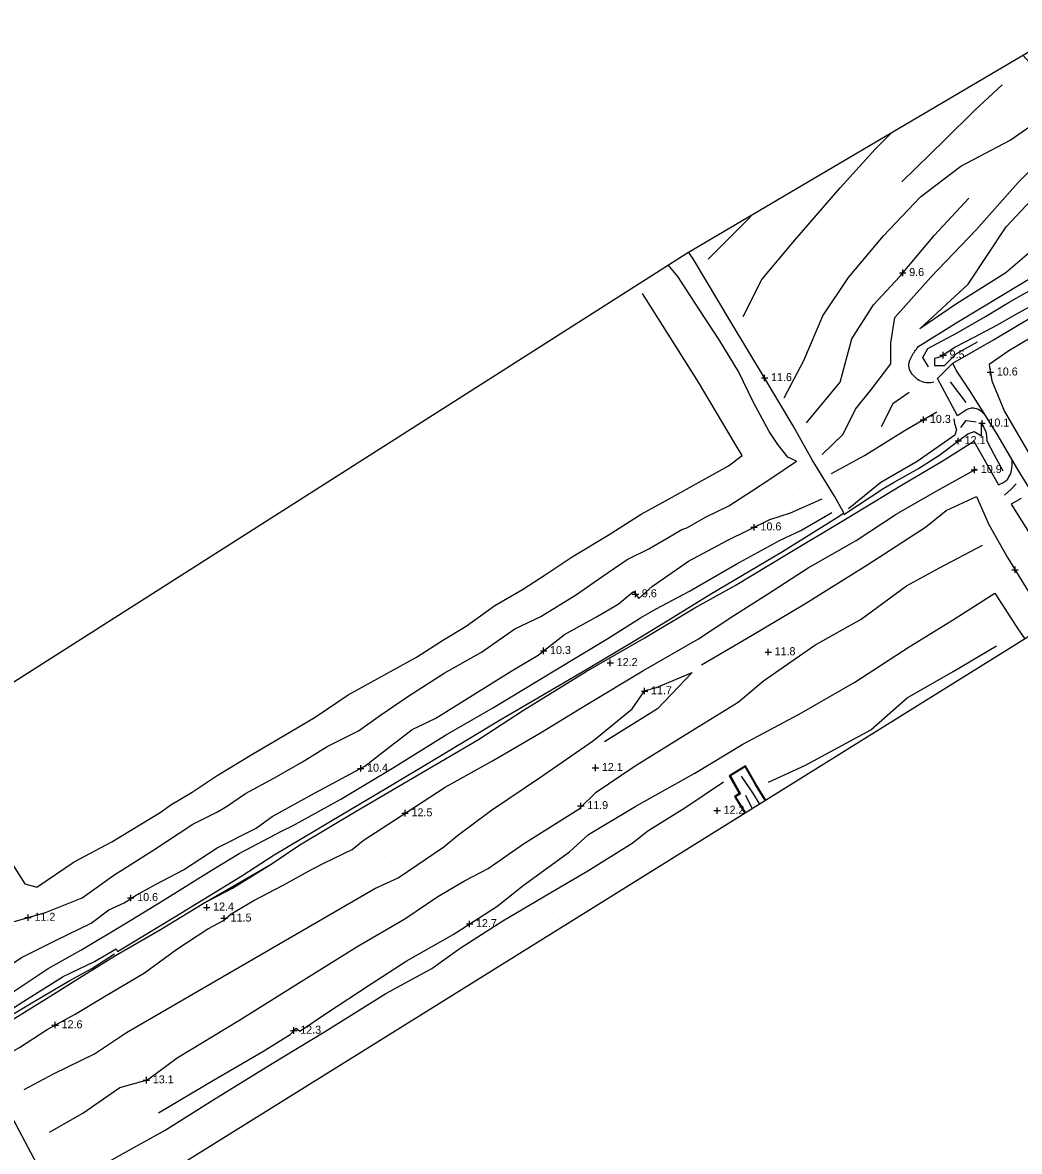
# Model space of a CAD drawing. Extents: x 2316231 to 2323598, y 363169 to 371906.
# Drawn here: x 2318197 to 2318819, y 368746 to 369451 of the extents above; entities that cross this region are included whole.
import ezdxf

# ---------------------------------------------------------------- set-up
doc = ezdxf.new("R2010")
doc.units = 0
for name, color, linetype in [('RD_DTM_BkLn1', 7, 'Continuous'), ('RD_DTM_Spot', 7, 'Continuous'), ('RD_DTM_TinHull', 7, 'Continuous'), ('RD_DTM_Void', 7, 'Continuous'), ('RD_EX_Road', 7, 'Continuous')]:
    doc.layers.add(name, color=color, linetype=linetype)

msp = doc.modelspace()

# ---------------------------------------------------------------- linework, layer by layer
at = {"layer": 'RD_DTM_BkLn1'}
for p, q in [((2318775.967, 369226.361), (2318785.842, 369213.429)), ((2318648.161, 368968.16), (2318652.337, 368959.64))]:
    msp.add_line(p, q, dxfattribs=at)
for points in [[(2318821.359, 369430.36), (2318833.929, 369416.318), (2318857.098, 369398.052), (2318876.357, 369378.589), (2318881.047, 369364.837), (2318878.846, 369345.713), (2318852.217, 369323.424), (2318829.708, 369310.579), (2318810.774, 369294.326), (2318779.947, 369275.055), (2318757.065, 369259.311), (2318787.149, 369287.192), (2318810.974, 369323.152), (2318829.939, 369343.202), (2318850.599, 369362.98), (2318851.312, 369380.511), (2318867.341, 369366.568), (2318854.815, 369340.791), (2318834.391, 369327.254)], [(2318745.754, 369351.081), (2318772.439, 369377.142), (2318791.386, 369395.915), (2318808.372, 369411.654)], [(2318672.457, 369216.258), (2318684.683, 369239.507), (2318696.612, 369267.472), (2318712.543, 369291.488), (2318734.369, 369317.42), (2318757.571, 369341.84), (2318782.715, 369360.973), (2318813.502, 369377.201), (2318833.127, 369390.992)], [(2318646.738, 369267.09), (2318658.497, 369290.078), (2318679.063, 369314.655), (2318707.239, 369347.357), (2318729.258, 369371.544), (2318739.835, 369382.275)], [(2318696.156, 369180.813), (2318709.127, 369193.648), (2318716.92, 369209.101), (2318727.145, 369221.844), (2318738.878, 369237.503), (2318738.899, 369250.681), (2318741.525, 369266.376), (2318763.849, 369291.732), (2318792.126, 369321.091), (2318818.401, 369350.83), (2318840.636, 369372.963)], [(2318686.257, 369200.608), (2318707.328, 369226.114), (2318714.681, 369253.184), (2318728.078, 369274.361), (2318744.561, 369292.12), (2318766.254, 369317.861), (2318787.707, 369340.881)], [(2318624.986, 369302.836), (2318649.023, 369327.096), (2318652.827, 369330.957)], [(2318318.77, 368957.723), (2318324.373, 368961.174), (2318336.268, 368969.133), (2318353.877, 368978.673), (2318371.753, 368989), (2318387.095, 368998.624), (2318406.746, 369008.273), (2318420.37, 369018.049), (2318437.477, 369029.753), (2318460.163, 369044.399), (2318483.473, 369057.538), (2318504.271, 369071.992), (2318520.582, 369079.772), (2318542.845, 369093.478), (2318558.505, 369104.544), (2318574.437, 369115.252), (2318587.901, 369122.009), (2318599.396, 369128.68), (2318608.425, 369134.1), (2318611.593, 369135.098), (2318623.626, 369142.006), (2318637.878, 369148.735), (2318651.977, 369158.019), (2318664.614, 369166.284), (2318680.163, 369176.779), (2318674.601, 369179.207), (2318668.507, 369187.106), (2318663.035, 369195.24), (2318653.26, 369213.459), (2318643.955, 369232.798), (2318632.274, 369251.839), (2318619.448, 369271.292), (2318606.057, 369291.965), (2318600.003, 369299.254)], [(2318762.396, 369235.636), (2318758.953, 369241.515), (2318762.061, 369246.99), (2318780.341, 369256.92), (2318798.121, 369267.164), (2318812.85, 369276.039), (2318827.134, 369284.153)], [(2318283.062, 368957.284), (2318289.69, 368962.204), (2318302.837, 368969.942), (2318318.494, 368980.519), (2318341.306, 368994.221), (2318360.427, 369005.33), (2318379.719, 369016.95), (2318400.359, 369030.891), (2318418.903, 369040.964), (2318442.895, 369054.421), (2318459.842, 369065.171), (2318474.008, 369073.679), (2318491.886, 369086.608), (2318508.996, 369096.533), (2318523.309, 369105.78), (2318540.092, 369117.032), (2318562.604, 369130.486), (2318583.169, 369143.699), (2318600.671, 369153.228), (2318620.737, 369164.534), (2318637.568, 369173.708), (2318646.161, 369180.169), (2318641.357, 369188.227), (2318618.971, 369226.018), (2318584.073, 369281.433)], [(2318826.841, 369273.793), (2318816.498, 369268.178), (2318805.278, 369261.612), (2318790.675, 369253.918), (2318779.065, 369248.01), (2318770.176, 369241.91), (2318766.135, 369240.761), (2318766.304, 369236.57), (2318772.499, 369236.514), (2318779.915, 369243.935), (2318793.144, 369251.302)], [(2318832.592, 369257.541), (2318812.619, 369245.59), (2318800.231, 369237.108), (2318802.052, 369226.964), (2318809.793, 369207.669), (2318825.043, 369181.817)], [(2318750.41, 369219.584), (2318740.178, 369212.452), (2318732.941, 369198.226)], [(2318701.907, 369169.084), (2318722.45, 369180.256), (2318747.982, 369196.034), (2318767.69, 369207.437)], [(2318709.65, 369143.355), (2318734.626, 369159.912), (2318741.031, 369163.578), (2318756.14, 369172.081), (2318769.615, 369180.784), (2318782.199, 369190.279), (2318786.932, 369193.728), (2318791.046, 369195.27), (2318795.568, 369192.513), (2318795.636, 369200.868), (2318798.444, 369194.622), (2318798.822, 369189.368), (2318803.243, 369181.061), (2318808.763, 369170.778)], [(2318782.632, 369197.833), (2318785.974, 369202.16), (2318792.141, 369201.316)], [(2318402.733, 368934.252), (2318409.74, 368939.752), (2318437.529, 368958.048), (2318460.766, 368973.121), (2318490.349, 368989.605), (2318520.259, 369007.09), (2318549.216, 369024.76), (2318584.098, 369045.788), (2318618.975, 369065.778), (2318641.04, 369080.403), (2318662.035, 369093.686), (2318687.284, 369110.05), (2318717.313, 369127.272), (2318742.18, 369143.709), (2318767.634, 369158.198), (2318792.32, 369171.998)], [(2318817.194, 369162.473), (2318813.906, 369159.136), (2318809.84, 369155.493)], [(2318342.854, 368947.622), (2318352.785, 368954.853), (2318379.326, 368969.479), (2318410.593, 368986.193), (2318422.064, 368995.241), (2318440.233, 369009.087), (2318454.977, 369016.22), (2318477.588, 369030.425), (2318502.965, 369046.119), (2318518.927, 369055.645), (2318535.313, 369068.498), (2318555.353, 369079.518), (2318568.859, 369087.361), (2318578.462, 369095.236), (2318581.674, 369091.006), (2318590.309, 369098.624), (2318612.582, 369114.275), (2318636.798, 369127.123), (2318663.391, 369140.34), (2318676.317, 369144.51), (2318696.094, 369153.179)], [(2318620.752, 369049.439), (2318652.447, 369068.132), (2318685.364, 369087.678), (2318724.622, 369112.217), (2318760.651, 369135.591), (2318773.455, 369145.992), (2318792.36, 369154.606), (2318800.146, 369137.114), (2318811.808, 369116.58), (2318830.247, 369086.414), (2318836.67, 369074.551)], [(2318358.747, 368945.649), (2318365.515, 368949.044), (2318395.767, 368965.752), (2318428.062, 368985.027), (2318461.092, 369005.599), (2318490.918, 369022.93), (2318528.795, 369045.769), (2318562.408, 369066.016), (2318582.697, 369078.86), (2318592.407, 369084.431), (2318613.307, 369095.494), (2318642.355, 369112.447), (2318669.828, 369127.355), (2318682.872, 369133.505), (2318702.137, 369144.72)], [(2318544.437, 368959.685), (2318555.063, 368970.106), (2318579.465, 368986.498), (2318616.711, 369009.662), (2318643.763, 369026.303), (2318659.435, 369039.566), (2318691.626, 369061.802), (2318720.408, 369078.159), (2318748.652, 369098.781), (2318769.278, 369110.024), (2318796.104, 369124.243)], [(2318538.409, 368932.692), (2318550.185, 368943.632), (2318579.786, 368961.226), (2318616.719, 368981.802), (2318646.49, 369000.028), (2318681.766, 369018.726), (2318716.513, 369038.8), (2318750.35, 369060.837), (2318777.474, 369077.37), (2318803.788, 369094.217), (2318818.721, 369071.471), (2318822.562, 369065.756)], [(2318662.671, 368976.32), (2318685.67, 368986.966), (2318726.454, 369008.906), (2318749.204, 369028.935), (2318777.89, 369045.305), (2318804.833, 369061.397)], [(2318459.925, 368935.824), (2318468.582, 368943.035), (2318489.746, 368958.883), (2318519.67, 368979.018), (2318553.395, 369002.38), (2318577.504, 369022.116), (2318585.442, 369033.426), (2318592.65, 369035.429), (2318615.069, 369044.825), (2318593.404, 369022.128), (2318560.218, 369001.425)], [(2318645.489, 368979.955), (2318652.537, 368969.629), (2318656.973, 368962.53)], [(2318577.558, 368938.118), (2318587.309, 368945.907), (2318610.315, 368960.218), (2318634.62, 368976.479)], [(2318069.796, 368913.667), (2318084.711, 368887.664), (2318096.568, 368861.51), (2318107.215, 368843.254), (2318128.886, 368852.799), (2318154.039, 368869.472), (2318177.979, 368887.147), (2318192.678, 368889.377), (2318211.476, 368894.92), (2318234.35, 368904.101), (2318254.106, 368918.162), (2318278.353, 368933.526), (2318303.385, 368950.103), (2318318.77, 368957.723)], [(2318213.86, 368757.804), (2318234.754, 368769.492), (2318257.787, 368785.628), (2318275.031, 368790.356), (2318293.619, 368804.155), (2318332.085, 368827.515), (2318374.324, 368853.935), (2318406.392, 368873.939), (2318435.674, 368891), (2318456.247, 368904.831), (2318472.828, 368914.627), (2318487.636, 368922.405), (2318509.681, 368937.665), (2318544.437, 368959.685)], [(2318182.938, 368937.212), (2318198.578, 368912.76), (2318205.987, 368910.734), (2318229.297, 368926.617), (2318252.791, 368939.057), (2318283.062, 368957.284)], [(2318057.547, 368908.988), (2318065.244, 368890.089), (2318075.451, 368863.434), (2318082.136, 368838.628), (2318084.803, 368825.3), (2318088.283, 368809.743), (2318118.752, 368824.828), (2318147.527, 368835.789), (2318174.581, 368852.254), (2318196.456, 368866.864), (2318218.021, 368877.528), (2318239.827, 368888.215), (2318250.977, 368896.519), (2318260.458, 368900.951), (2318268.087, 368905.712), (2318280.148, 368912.377), (2318297.498, 368921.473), (2318318.589, 368935.183), (2318342.854, 368947.622)], [(2318067.828, 368850.02), (2318072.967, 368828.154), (2318077.929, 368807.936), (2318084.572, 368796.477), (2318102.745, 368802.406), (2318129.775, 368813.72), (2318161.786, 368829.428), (2318186.859, 368842.43), (2318213.06, 368859.908), (2318233.376, 368871.453), (2318260.995, 368887.699), (2318284.458, 368902.258), (2318314.707, 368921.05), (2318332.361, 368931.626), (2318358.747, 368945.649)], [(2318231.245, 368728.124), (2318257.55, 368743.11), (2318285.998, 368758.946), (2318316.356, 368778.038), (2318352.81, 368800.5), (2318385.467, 368820.261), (2318423.718, 368844.319), (2318452.479, 368859.998), (2318470.209, 368872.547), (2318496.711, 368889.663), (2318530.355, 368909.507), (2318549.888, 368920.861), (2318577.558, 368938.118)], [(2318098.707, 368755.444), (2318123.229, 368769.712), (2318150.076, 368785.43), (2318172.668, 368797.801), (2318195.225, 368810.641), (2318212.484, 368821.831), (2318229.834, 368831.361), (2318248.296, 368842.501), (2318273.216, 368857.141), (2318293.274, 368871.923), (2318312.653, 368884.626), (2318322.461, 368889.888), (2318327.176, 368894.053), (2318341.431, 368902.458), (2318359.636, 368911.866), (2318377.83, 368921.923), (2318385.469, 368925.998), (2318402.733, 368934.252)], [(2318197.996, 368784.279), (2318216.9, 368794.31), (2318241.887, 368806.615), (2318261.882, 368819.954), (2318416.893, 368909.875), (2318431.53, 368916.583), (2318459.925, 368935.824)], [(2318281.834, 368769.75), (2318316.31, 368790.206), (2318347.074, 368808.046), (2318364.102, 368818.756), (2318367.829, 368822.695), (2318370.16, 368820.764), (2318386.189, 368831.512), (2318414.548, 368850.321), (2318436.458, 368864.546), (2318465.787, 368881.138), (2318493.132, 368898.697), (2318509.588, 368911.743), (2318538.409, 368932.692)], [(2318309.704, 368900.578), (2318328.017, 368910.142), (2318352.275, 368924.988)], [(2318082.182, 368776.745), (2318092.807, 368781.837), (2318111.618, 368792.976), (2318132.239, 368801.09), (2318157.872, 368811.637), (2318169.898, 368818.783), (2318201.892, 368837.824), (2318226.221, 368852.177), (2318240.223, 368859.969), (2318254.395, 368869.012)], [(2318128.541, 368755.619), (2318149.504, 368765.935), (2318167.781, 368775.367), (2318181.682, 368781.137), (2318192.93, 368762.507), (2318224.475, 368702.806), (2318242.058, 368675.521), (2318221.599, 368664.71), (2318205.84, 368656.549), (2318202.139, 368670.313), (2318152.285, 368755.23), (2318177.664, 368770.748)]]:
    msp.add_lwpolyline(points, dxfattribs=at)
at = {"layer": 'RD_DTM_Spot'}
for p, q in [((2318799.356, 369383.745), (2318799.356, 369383.745)), ((2318804.714, 369356.262), (2318804.714, 369356.262)), ((2318770.725, 369339.407), (2318770.725, 369339.407)), ((2318726.102, 369334.33), (2318726.102, 369334.33)), ((2318698.679, 369308.667), (2318698.679, 369308.667)), ((2318640.887, 369291.627), (2318640.887, 369291.627)), ((2318679.995, 369280.821), (2318679.995, 369280.821)), ((2318747.63, 369256.03), (2318747.63, 369256.03)), ((2318660.828, 369249.755), (2318660.828, 369249.755)), ((2318724.297, 369240.85), (2318724.297, 369240.85)), ((2318817.624, 369237.255), (2318817.624, 369237.255)), ((2318743.01, 369226.451), (2318743.01, 369226.451)), ((2318788.257, 369232.301), (2318788.257, 369232.301)), ((2318813.766, 369225.518), (2318813.766, 369225.518)), ((2318683.081, 369216.322), (2318683.081, 369216.322)), ((2318759.815, 369214.891), (2318759.815, 369214.891)), ((2318696.445, 369197.224), (2318696.445, 369197.224)), ((2318721.345, 369194.861), (2318721.345, 369194.861)), ((2318768.343, 369195.437), (2318768.343, 369195.437)), ((2318660.539, 369176.858), (2318660.539, 369176.858)), ((2318640.541, 369162.496), (2318640.541, 369162.496)), ((2318715.767, 369162.482), (2318715.767, 369162.482)), ((2318797.199, 369162.22), (2318797.199, 369162.22)), ((2318682.043, 369159.711), (2318682.043, 369159.711)), ((2318616.703, 369148.786), (2318616.703, 369148.786)), ((2318592.793, 369135.101), (2318592.793, 369135.101)), ((2318784.596, 369135.381), (2318784.596, 369135.381)), ((2318572.252, 369124.204), (2318572.252, 369124.204)), ((2318761.756, 369120.879), (2318761.756, 369120.879)), ((2318599.962, 369115.965), (2318599.962, 369115.965)), ((2318550.177, 369109.984), (2318550.177, 369109.984)), ((2318579.406, 369106.738), (2318579.406, 369106.738)), ((2318802.451, 369107.749), (2318802.451, 369107.749)), ((2318527.633, 369099.491), (2318527.633, 369099.491)), ((2318536.497, 369105.365), (2318536.497, 369105.365)), ((2318540.367, 369103.41), (2318540.367, 369103.41)), ((2318524.053, 369095.141), (2318524.053, 369095.141)), ((2318561.777, 369093.498), (2318561.777, 369093.498)), ((2318596.707, 369094.054), (2318596.707, 369094.054)), ((2318778.874, 369096.151), (2318778.874, 369096.151)), ((2318503.091, 369081.38), (2318503.091, 369081.38)), ((2318535.534, 369078.894), (2318535.534, 369078.894)), ((2318572.563, 369081.301), (2318572.563, 369081.301)), ((2318753.483, 369079.895), (2318753.483, 369079.895)), ((2318799.028, 369072.028), (2318799.028, 369072.028)), ((2318510, 369062.806), (2318510, 369062.806)), ((2318662.43, 369057.551), (2318662.43, 369057.551)), ((2318767.141, 369057.668), (2318767.141, 369057.668)), ((2318702.107, 369045.955), (2318702.107, 369045.955)), ((2318637.5, 369038.333), (2318637.5, 369038.333)), ((2318422.463, 369032.529), (2318422.463, 369032.529)), ((2318674.125, 369029.653), (2318674.125, 369029.653)), ((2318401.623, 369021.418), (2318401.623, 369021.418)), ((2318567.469, 369025.213), (2318567.469, 369025.213)), ((2318612.413, 369023.174), (2318612.413, 369023.174)), ((2318394.702, 369019.593), (2318394.702, 369019.593)), ((2318653.337, 369017.312), (2318653.337, 369017.312)), ((2318383.592, 369009.015), (2318383.592, 369009.015)), ((2318387.007, 369013.713), (2318387.007, 369013.713)), ((2318394.074, 369013.783), (2318394.074, 369013.783)), ((2318422.317, 369007.093), (2318422.317, 369007.093)), ((2318542.501, 369007.678), (2318542.501, 369007.678)), ((2318582.521, 369002.43), (2318582.521, 369002.43)), ((2318629.625, 369002.54), (2318629.625, 369002.54)), ((2318687.706, 369004.263), (2318687.706, 369004.263)), ((2318410.815, 368998.881), (2318410.815, 368998.881)), ((2318396.242, 368990.244), (2318396.242, 368990.244)), ((2318510.768, 368986.323), (2318510.768, 368986.323)), ((2318659.159, 368989.409), (2318659.159, 368989.409)), ((2318551.745, 368983.719), (2318551.745, 368983.719)), ((2318517.215, 368959.478), (2318517.215, 368959.478)), ((2318630.587, 368958.536), (2318630.587, 368958.536)), ((2318454.996, 368951.892), (2318454.996, 368951.892)), ((2318606.382, 368941.02), (2318606.382, 368941.02)), ((2318422.829, 368929.691), (2318422.829, 368929.691)), ((2318509.613, 368922.947), (2318509.613, 368922.947)), ((2318230.087, 368913.678), (2318230.087, 368913.678)), ((2318203.414, 368901.16), (2318203.414, 368901.16)), ((2318476.181, 368901.478), (2318476.181, 368901.478)), ((2318527.603, 368894.903), (2318527.603, 368894.903)), ((2318211.977, 368887.469), (2318211.977, 368887.469)), ((2318447.201, 368884.536), (2318447.201, 368884.536)), ((2318498.849, 368876.877), (2318498.849, 368876.877)), ((2318416.159, 368865.89), (2318416.159, 368865.89)), ((2318469.295, 368856.146), (2318469.295, 368856.146)), ((2318390.034, 368844.935), (2318390.034, 368844.935)), ((2318242.783, 368825.604), (2318242.783, 368825.604)), ((2318361.381, 368829.461), (2318361.381, 368829.461)), ((2318337.153, 368817.19), (2318337.153, 368817.19)), ((2318221.618, 368811.088), (2318221.618, 368811.088)), ((2318198.098, 368798.154), (2318198.098, 368798.154)), ((2318306.233, 368799.567), (2318306.233, 368799.567)), ((2318241.686, 368791.536), (2318241.686, 368791.536)), ((2318272.61, 368778.483), (2318272.61, 368778.483)), ((2318210.501, 368773.757), (2318210.501, 368773.757)), ((2318250.869, 368758.986), (2318250.869, 368758.986))]:
    msp.add_line(p, q, dxfattribs=at)
at = {"layer": 'RD_DTM_TinHull'}
for points in [[(2318500.627, 367718.473), (2317350.395, 369314.708), (2317732.783, 369650.329), (2318062.064, 369676.571), (2318100.376, 368980.922), (2318611.552, 369306.612), (2319043.87, 369561.601), (2319323.163, 369792.894), (2318905.258, 370457.792), (2319170.205, 370651.465)], [(2321400.963, 368599.408), (2321534.916, 368777.939), (2321271.463, 369044.178), (2321175.279, 369261.496), (2321099.267, 369551.406), (2321096.219, 369852.637), (2320858.06, 369744.011), (2320482.587, 369669.607), (2320232.924, 369604.892), (2319951.333, 369602.051), (2320092.085, 369259.27), (2319866.523, 369058.699), (2319771.694, 369171.639), (2319557.442, 369523.873), (2318254.179, 368711.432)]]:
    msp.add_lwpolyline(points, dxfattribs=at)
at = {"layer": 'RD_DTM_Void'}
for p, q in [((2318746.419, 369292.325), (2318746.419, 369296.325)), ((2318744.419, 369294.325), (2318748.419, 369294.325)), ((2318769.621, 369242.902), (2318773.621, 369242.902)), ((2318771.621, 369240.902), (2318771.621, 369244.902)), ((2318801.109, 369230.22), (2318801.109, 369234.22)), ((2318658.196, 369228.713), (2318662.196, 369228.713)), ((2318660.196, 369226.713), (2318660.196, 369230.713)), ((2318799.109, 369232.22), (2318803.109, 369232.22)), ((2318759.36, 369200.617), (2318759.36, 369204.617)), ((2318757.36, 369202.617), (2318761.36, 369202.617)), ((2318793.865, 369200.359), (2318797.865, 369200.359)), ((2318795.865, 369198.359), (2318795.865, 369202.359)), ((2318781.022, 369187.391), (2318781.022, 369191.391)), ((2318779.022, 369189.391), (2318783.022, 369189.391)), ((2318789.118, 369171.326), (2318793.118, 369171.326)), ((2318791.118, 369169.326), (2318791.118, 369173.326)), ((2318651.626, 369135.487), (2318655.626, 369135.487)), ((2318653.626, 369133.487), (2318653.626, 369137.487)), ((2318814.464, 369108.963), (2318818.464, 369108.963)), ((2318816.464, 369106.963), (2318816.464, 369110.963)), ((2318577.607, 369093.728), (2318581.607, 369093.728)), ((2318579.607, 369091.728), (2318579.607, 369095.728)), ((2318520.289, 369058.282), (2318524.289, 369058.282)), ((2318522.289, 369056.282), (2318522.289, 369060.282)), ((2318660.43, 369057.551), (2318664.43, 369057.551)), ((2318662.43, 369055.551), (2318662.43, 369059.551)), ((2318561.88, 369050.788), (2318565.88, 369050.788)), ((2318563.88, 369048.788), (2318563.88, 369052.788)), ((2318585.264, 369031.173), (2318585.264, 369035.173)), ((2318583.264, 369033.173), (2318587.264, 369033.173)), ((2318408.102, 368982.862), (2318408.102, 368986.862)), ((2318554.63, 368983.232), (2318554.63, 368987.232)), ((2318406.102, 368984.862), (2318410.102, 368984.862)), ((2318552.63, 368985.232), (2318556.63, 368985.232)), ((2318435.834, 368954.932), (2318435.834, 368958.932)), ((2318543.492, 368961.454), (2318547.492, 368961.454)), ((2318545.492, 368959.454), (2318545.492, 368963.454)), ((2318628.587, 368958.536), (2318632.587, 368958.536)), ((2318630.587, 368956.536), (2318630.587, 368960.536)), ((2318433.834, 368956.932), (2318437.834, 368956.932)), ((2318262.617, 368904.01), (2318266.617, 368904.01)), ((2318264.617, 368902.01), (2318264.617, 368906.01)), ((2318310.021, 368898.094), (2318314.021, 368898.094)), ((2318312.021, 368896.094), (2318312.021, 368900.094)), ((2318198.543, 368891.696), (2318202.543, 368891.696)), ((2318200.543, 368889.696), (2318200.543, 368893.696)), ((2318320.921, 368891.246), (2318324.921, 368891.246)), ((2318322.921, 368889.246), (2318322.921, 368893.246)), ((2318474.048, 368887.727), (2318478.048, 368887.727)), ((2318476.048, 368885.727), (2318476.048, 368889.727)), ((2318215.458, 368824.564), (2318219.458, 368824.564)), ((2318217.458, 368822.564), (2318217.458, 368826.564)), ((2318364.39, 368821.174), (2318368.39, 368821.174)), ((2318366.39, 368819.174), (2318366.39, 368823.174)), ((2318272.404, 368790.184), (2318276.404, 368790.184)), ((2318274.404, 368788.184), (2318274.404, 368792.184))]:
    msp.add_line(p, q, dxfattribs=at)
at = {"layer": 'RD_EX_Road'}
for points in [[(2318755.848, 369248.133), (2318780.065, 369263.344), (2318821.438, 369288.241), (2318868.879, 369316.306), (2318905.56, 369338.852), (2318907.775, 369353.666), (2318902.989, 369376.527), (2318885.663, 369398.033), (2318864.969, 369417.014), (2318841.249, 369434.936), (2318836.61, 369439.355)], [(2318333.907, 368917.711), (2318354.21, 368930.817), (2318389.056, 368951.63), (2318424.872, 368973.011), (2318455.359, 368991.317), (2318495.139, 369015.208), (2318518.703, 369029.003), (2318549.248, 369046.807), (2318578.514, 369064.319), (2318603.075, 369079.278), (2318625.973, 369093.387), (2318671.426, 369120.22), (2318706.733, 369142.416), (2318709.596, 369144.466), (2318703.85, 369154.917), (2318689.8, 369177.468), (2318678.035, 369198.801), (2318659.553, 369229.791), (2318639.377, 369263.332), (2318615.498, 369303.136), (2318612.738, 369307.311)], [(2318777.591, 369237.848), (2318777.591, 369237.848), (2318803.058, 369252.516), (2318828.743, 369267.803)], [(2318784.99, 369208.038), (2318780.486, 369205.054), (2318768.064, 369228.444), (2318777.591, 369237.848)], [(2318865.563, 369092.563), (2318849.372, 369120.787), (2318831.951, 369149.301), (2318818.114, 369171.6), (2318805.302, 369193.512), (2318796.542, 369207.536), (2318788.019, 369221.081), (2318779.717, 369233.587), (2318777.591, 369237.848)], [(2318778.256, 369203.144), (2318778.682, 369200.158), (2318779.951, 369196.307), (2318778.93, 369193.006), (2318755.447, 369176.49), (2318732.638, 369163.3), (2318716.85, 369150.491), (2318712.594, 369147.016)], [(2318352.275, 368924.988), (2318370.143, 368937.083), (2318405.312, 368958.062), (2318440.36, 368978.731), (2318481.646, 369002.961), (2318509.65, 369021.256), (2318548.87, 369045.329), (2318584.958, 369066.291), (2318616.702, 369085.199), (2318641.712, 369099.141), (2318673.769, 369118.501), (2318710.602, 369140.533), (2318745.51, 369161.764), (2318771.086, 369176.801), (2318790.835, 369189.112), (2318806.067, 369161.947), (2318808.292, 369162.938)], [(2318820.357, 369153.349), (2318814.012, 369149.825), (2318832.952, 369119.632), (2318850.677, 369089.769), (2318853.516, 369085.053)], [(2318660.969, 368965.021), (2318654.952, 368974.832), (2318648.233, 368986.494), (2318638.162, 368980.328), (2318644.382, 368969.17), (2318641.411, 368967.252), (2318647.747, 368956.779)], [(2318660.544, 368964.756), (2318654.522, 368974.577), (2318648.056, 368985.8), (2318638.832, 368980.152), (2318645.047, 368969.004), (2318642.091, 368967.095), (2318648.172, 368957.043)], [(2318309.704, 368900.578), (2318352.275, 368924.988), (2318352.275, 368924.988)], [(2318057.434, 368763.766), (2318061.197, 368767.537), (2318059.386, 368776.085), (2318077.849, 368782.327), (2318112.628, 368797.968), (2318148.726, 368811.681), (2318176.195, 368825.713), (2318199.455, 368840.489), (2318222.497, 368854.893), (2318242.001, 368864.177), (2318255.57, 368872.283), (2318256.336, 368870.572), (2318292.127, 368892.265), (2318333.907, 368917.711)], [(2318061.728, 368751.469), (2318065.914, 368750.702), (2318070.391, 368750.704), (2318086.678, 368757.925), (2318107.403, 368769.854), (2318129.941, 368784.812), (2318157.449, 368800), (2318172.774, 368807.669), (2318169.3, 368814.909), (2318192.185, 368828.916), (2318216.443, 368843.846), (2318232.664, 368854.016), (2318255.031, 368867.939), (2318283.216, 368884.365), (2318309.704, 368900.578)]]:
    msp.add_lwpolyline(points, dxfattribs=at)
for points in [[(2318765.771, 369226.033), (2318762.152, 369225.563), (2318753.828, 369229.367), (2318750.143, 369236.978), (2318752.07, 369242.363), (2318755.848, 369248.133)], [(2318798.146, 369204.968), (2318795.481, 369207.733), (2318791.42, 369209.652), (2318788.376, 369209.596), (2318784.99, 369208.038)], [(2318808.292, 369162.938), (2318810.699, 369164.393), (2318812.465, 369166.473), (2318814.255, 369170.976), (2318814.619, 369177.578)]]:
    msp.add_spline(points, degree=3, dxfattribs=at)

# ---------------------------------------------------------------- texts
at = {"layer": 'RD_DTM_Void'}
for s, p in [('9.6', (2318750.419, 369292.325)), ('9.5', (2318775.621, 369240.902)), ('10.6', (2318805.109, 369230.22)), ('11.6', (2318664.196, 369226.713)), ('10.3', (2318763.36, 369200.617)), ('10.1', (2318799.865, 369198.359)), ('12.1', (2318785.022, 369187.391)), ('10.9', (2318795.118, 369169.326)), ('10.6', (2318657.626, 369133.487)), ('9.6', (2318583.607, 369091.728)), ('10.3', (2318526.289, 369056.282)), ('11.8', (2318666.43, 369055.551)), ('12.2', (2318567.88, 369048.788)), ('11.7', (2318589.264, 369031.173)), ('10.4', (2318412.102, 368982.862)), ('12.1', (2318558.63, 368983.232)), ('12.5', (2318439.834, 368954.932)), ('11.9', (2318549.492, 368959.454)), ('12.2', (2318634.587, 368956.536)), ('10.6', (2318268.617, 368902.01)), ('12.4', (2318316.021, 368896.094)), ('11.2', (2318204.543, 368889.696)), ('11.5', (2318326.921, 368889.246)), ('12.7', (2318480.048, 368885.727)), ('12.6', (2318221.458, 368822.564)), ('12.3', (2318370.39, 368819.174)), ('13.1', (2318278.404, 368788.184))]:
    msp.add_text(s, height=5, dxfattribs=at).set_placement(p)

doc.saveas('drawing.dxf')
